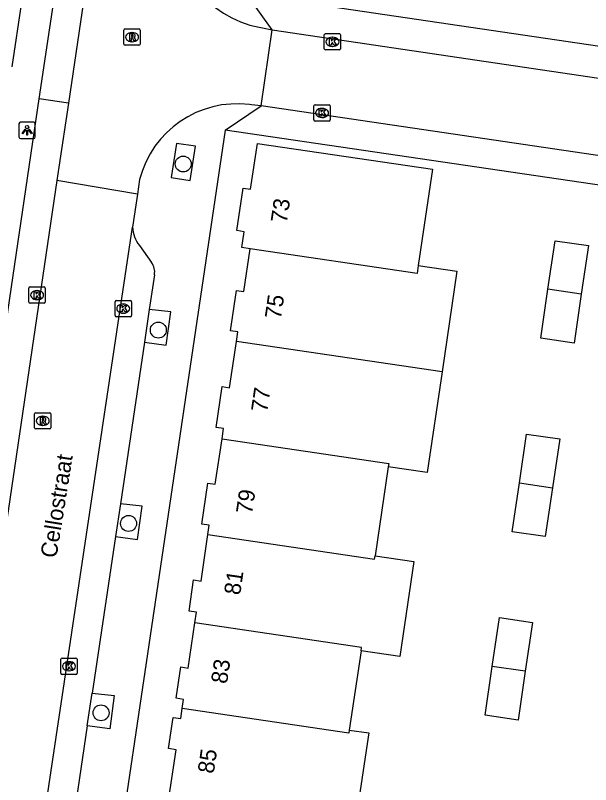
# Model space of a CAD drawing. Extents: x 164150 to 165261, y 382513 to 383432.
# Drawn here: x 164393.69 to 164428.99, y 382925.13 to 382972.36 of the extents above; entities that cross this region are included whole.
import ezdxf

# ---------------------------------------------------------------- set-up
doc = ezdxf.new("R2010")
doc.units = 0
for name, color, linetype in [('IMGEO_Boom', 7, 'Continuous'), ('IMGEO_Kolk', 7, 'Continuous'), ('IMGEO_Lichtpunt', 7, 'Continuous'), ('IMGEO_Openbare_ruimte_label', 7, 'Continuous'), ('IMGEO_Pand', 7, 'Continuous'), ('IMGEO_Pand_nummerreeks', 7, 'Continuous'), ('IMGEO_Parkeervlak_open', 7, 'Continuous'), ('IMGEO_Rijbaan_lokaal_open', 7, 'Continuous'), ('IMGEO_Rioolput', 7, 'Continuous'), ('IMGEO_Voetpad_open', 7, 'Continuous')]:
    doc.layers.add(name, color=color, linetype=linetype)

msp = doc.modelspace()

# ---------------------------------------------------------------- linework, layer by layer
at = {"layer": 'IMGEO_Boom'}
for centre in [(164403.987, 382963.232), (164402.46, 382953.036), (164400.635, 382941.165), (164398.944, 382929.538)]:
    msp.add_circle(centre, 0.489, dxfattribs=at)
at = {"layer": 'IMGEO_Kolk'}
for p, q in [((164412.645, 382970.309), (164412.645, 382971.161)), ((164412.72, 382971.235), (164413.572, 382971.235)), ((164413.646, 382971.161), (164413.646, 382970.309)), ((164413.133, 382971.015), (164413.158, 382971.015)), ((164413.572, 382970.235), (164412.72, 382970.235)), ((164413.156, 382970.455), (164413.131, 382970.455)), ((164412.009, 382965.942), (164412.009, 382966.794)), ((164412.084, 382966.868), (164412.936, 382966.868)), ((164412.497, 382966.648), (164412.522, 382966.648)), ((164413.01, 382966.794), (164413.01, 382965.942)), ((164412.52, 382966.088), (164412.495, 382966.088)), ((164412.936, 382965.868), (164412.084, 382965.868)), ((164394.519, 382954.76), (164394.519, 382955.612)), ((164394.594, 382955.686), (164395.446, 382955.686)), ((164395.52, 382955.612), (164395.52, 382954.76)), ((164395.007, 382955.466), (164395.032, 382955.466)), ((164395.446, 382954.686), (164394.594, 382954.686)), ((164395.03, 382954.906), (164395.005, 382954.906)), ((164399.805, 382953.928), (164399.805, 382954.78)), ((164399.88, 382954.854), (164400.732, 382954.854)), ((164400.293, 382954.634), (164400.318, 382954.634)), ((164400.806, 382954.78), (164400.806, 382953.928)), ((164400.732, 382953.854), (164399.88, 382953.854)), ((164400.316, 382954.074), (164400.291, 382954.074)), ((164396.477, 382931.973), (164396.477, 382932.825)), ((164396.552, 382932.899), (164397.404, 382932.899)), ((164396.965, 382932.679), (164396.99, 382932.679)), ((164397.478, 382932.825), (164397.478, 382931.973)), ((164396.988, 382932.119), (164396.963, 382932.119)), ((164397.404, 382931.899), (164396.552, 382931.899))]:
    msp.add_line(p, q, dxfattribs=at)
for points in [[(164412.645, 382970.309), (164412.645, 382971.161)], [(164412.72, 382971.235), (164413.572, 382971.235)], [(164413.646, 382971.161), (164413.646, 382970.309)], [(164412.966, 382970.935), (164413.089, 382970.935), (164413.089, 382970.784), (164413.219, 382970.935), (164413.383, 382970.935), (164413.237, 382970.784), (164413.39, 382970.535), (164413.238, 382970.535), (164413.153, 382970.699), (164413.089, 382970.632), (164413.089, 382970.535), (164412.966, 382970.535), (164412.966, 382970.935)], [(164413.572, 382970.235), (164412.72, 382970.235)], [(164412.009, 382965.942), (164412.009, 382966.794)], [(164412.084, 382966.868), (164412.936, 382966.868)], [(164412.33, 382966.568), (164412.453, 382966.568), (164412.453, 382966.417), (164412.583, 382966.568), (164412.747, 382966.568), (164412.601, 382966.417), (164412.754, 382966.168), (164412.602, 382966.168), (164412.517, 382966.332), (164412.453, 382966.265), (164412.453, 382966.168), (164412.33, 382966.168), (164412.33, 382966.568)], [(164413.01, 382966.794), (164413.01, 382965.942)], [(164412.936, 382965.868), (164412.084, 382965.868)], [(164394.519, 382954.76), (164394.519, 382955.612)], [(164394.594, 382955.686), (164395.446, 382955.686)], [(164395.52, 382955.612), (164395.52, 382954.76)], [(164394.84, 382955.386), (164394.963, 382955.386), (164394.963, 382955.235), (164395.093, 382955.386), (164395.257, 382955.386), (164395.111, 382955.235), (164395.264, 382954.986), (164395.112, 382954.986), (164395.027, 382955.15), (164394.963, 382955.083), (164394.963, 382954.986), (164394.84, 382954.986), (164394.84, 382955.386)], [(164395.446, 382954.686), (164394.594, 382954.686)], [(164399.805, 382953.928), (164399.805, 382954.78)], [(164399.88, 382954.854), (164400.732, 382954.854)], [(164400.806, 382954.78), (164400.806, 382953.928)], [(164400.126, 382954.554), (164400.249, 382954.554), (164400.249, 382954.403), (164400.379, 382954.554), (164400.543, 382954.554), (164400.397, 382954.403), (164400.55, 382954.154), (164400.398, 382954.154), (164400.313, 382954.318), (164400.249, 382954.251), (164400.249, 382954.154), (164400.126, 382954.154), (164400.126, 382954.554)], [(164400.732, 382953.854), (164399.88, 382953.854)], [(164396.477, 382931.973), (164396.477, 382932.825)], [(164396.552, 382932.899), (164397.404, 382932.899)], [(164396.798, 382932.599), (164396.921, 382932.599), (164396.921, 382932.448), (164397.051, 382932.599), (164397.215, 382932.599), (164397.069, 382932.448), (164397.222, 382932.199), (164397.07, 382932.199), (164396.985, 382932.363), (164396.921, 382932.296), (164396.921, 382932.199), (164396.798, 382932.199), (164396.798, 382932.599)], [(164397.478, 382932.825), (164397.478, 382931.973)], [(164397.404, 382931.899), (164396.552, 382931.899)]]:
    msp.add_lwpolyline(points, dxfattribs=at)
for centre, start, end in [((164412.722, 382971.159), 91.552, 178.448), ((164412.722, 382971.159), 91.552, 178.448), ((164413.57, 382971.159), 1.552, 88.448), ((164413.57, 382971.159), 1.552, 88.448), ((164412.722, 382970.311), 181.552, 268.448), ((164412.722, 382970.311), 181.552, 268.448), ((164413.57, 382970.311), 271.552, 358.448), ((164413.57, 382970.311), 271.552, 358.448), ((164412.086, 382966.792), 91.552, 178.448), ((164412.086, 382966.792), 91.552, 178.448), ((164412.934, 382966.792), 1.552, 88.448), ((164412.934, 382966.792), 1.552, 88.448), ((164412.086, 382965.944), 181.552, 268.448), ((164412.086, 382965.944), 181.552, 268.448), ((164412.934, 382965.944), 271.552, 358.448), ((164412.934, 382965.944), 271.552, 358.448), ((164394.596, 382955.61), 91.552, 178.448), ((164394.596, 382955.61), 91.552, 178.448), ((164395.444, 382955.61), 1.552, 88.448), ((164395.444, 382955.61), 1.552, 88.448), ((164394.596, 382954.762), 181.552, 268.448), ((164394.596, 382954.762), 181.552, 268.448), ((164395.444, 382954.762), 271.552, 358.448), ((164395.444, 382954.762), 271.552, 358.448), ((164399.882, 382954.778), 91.552, 178.448), ((164399.882, 382954.778), 91.552, 178.448), ((164400.73, 382954.778), 1.552, 88.448), ((164400.73, 382954.778), 1.552, 88.448), ((164399.882, 382953.93), 181.552, 268.448), ((164399.882, 382953.93), 181.552, 268.448), ((164400.73, 382953.93), 271.552, 358.448), ((164400.73, 382953.93), 271.552, 358.448), ((164396.554, 382932.823), 91.552, 178.448), ((164396.554, 382932.823), 91.552, 178.448), ((164397.402, 382932.823), 1.552, 88.448), ((164397.402, 382932.823), 1.552, 88.448), ((164396.554, 382931.975), 181.552, 268.448), ((164396.554, 382931.975), 181.552, 268.448), ((164397.402, 382931.975), 271.552, 358.448), ((164397.402, 382931.975), 271.552, 358.448)]:
    msp.add_arc(centre, 0.0765, start, end, dxfattribs=at)
for centre, major_axis, ratio, start_param, end_param in [((164413.132, 382970.735), (-0.387, 0.002), 0.722429, 4.712389, 7.853982), ((164413.157, 382970.735), (-0.39, 0.002), 0.717154, 1.570796, 4.712389), ((164412.496, 382966.368), (-0.387, 0.002), 0.722429, 4.712389, 7.853982), ((164412.521, 382966.368), (-0.39, 0.002), 0.717154, 1.570796, 4.712389), ((164395.006, 382955.186), (-0.387, 0.002), 0.722429, 4.712389, 7.853982), ((164395.031, 382955.186), (-0.39, 0.002), 0.717154, 1.570796, 4.712389), ((164400.292, 382954.354), (-0.387, 0.002), 0.722429, 4.712389, 7.853982), ((164400.317, 382954.354), (-0.39, 0.002), 0.717154, 1.570796, 4.712389), ((164396.964, 382932.399), (-0.387, 0.002), 0.722429, 4.712389, 7.853982), ((164396.989, 382932.399), (-0.39, 0.002), 0.717154, 1.570796, 4.712389)]:
    msp.add_ellipse(centre, major_axis=major_axis, ratio=ratio, start_param=start_param, end_param=end_param, dxfattribs=at)
at = {"layer": 'IMGEO_Lichtpunt'}
for p, q in [((164393.909, 382965.703), (164393.909, 382964.896)), ((164393.909, 382965.703), (164393.909, 382964.896)), ((164394.811, 382965.798), (164394.003, 382965.798)), ((164394.811, 382965.798), (164394.003, 382965.798)), ((164394.905, 382964.896), (164394.905, 382965.703)), ((164394.905, 382964.896), (164394.905, 382965.703)), ((164394.003, 382964.802), (164394.811, 382964.802)), ((164394.003, 382964.802), (164394.811, 382964.802))]:
    msp.add_line(p, q, dxfattribs=at)
for points in [[(164394.283, 382965.367), (164394.322, 382965.339), (164394.134, 382965.077), (164394.096, 382965.104), (164394.283, 382965.367)], [(164394.385, 382965.319), (164394.432, 382965.319), (164394.432, 382964.997), (164394.385, 382964.997), (164394.385, 382965.319)], [(164394.495, 382965.339), (164394.533, 382965.366), (164394.72, 382965.104), (164394.681, 382965.076), (164394.495, 382965.339)]]:
    msp.add_lwpolyline(points, dxfattribs=at)
msp.add_circle((164394.408, 382965.501), 0.0994, dxfattribs=at)
for centre, start, end in [((164394.003, 382965.703), 90, 180), ((164394.003, 382965.703), 90, 180), ((164394.811, 382965.703), 0, 90), ((164394.811, 382965.703), 0, 90), ((164394.003, 382964.896), 180, 270), ((164394.003, 382964.896), 180, 270), ((164394.811, 382964.896), 270, 0), ((164394.811, 382964.896), 270, 360)]:
    msp.add_arc(centre, 0.0946, start, end, dxfattribs=at)
at = {"layer": 'IMGEO_Pand'}
for points in [[(164408.091, 382958.021), (164407.589, 382958.097), (164407.736, 382959.075), (164407.281, 382959.143), (164407.67, 382961.751), (164408.125, 382961.681), (164408.545, 382964.496), (164419.288, 382962.906), (164418.415, 382957.004)], [(164426.369, 382955.541), (164426.808, 382958.517), (164428.857, 382958.234), (164428.412, 382955.238)], [(164407.253, 382952.345), (164407.338, 382952.921), (164406.884, 382952.988), (164407.25, 382955.475), (164407.705, 382955.408), (164408.091, 382958.021)], [(164418.415, 382957.004), (164418.341, 382956.503), (164408.091, 382958.021)], [(164418.415, 382957.004), (164420.787, 382956.653), (164419.872, 382950.476)], [(164428.412, 382955.238), (164427.968, 382952.241), (164425.925, 382952.531), (164426.369, 382955.541)], [(164428.412, 382955.238), (164426.369, 382955.541)], [(164406.37, 382946.365), (164406.462, 382946.988), (164406.006, 382947.057), (164406.38, 382949.567), (164406.833, 382949.501), (164407.253, 382952.345)], [(164419.872, 382950.476), (164407.253, 382952.345)], [(164419.872, 382950.476), (164418.957, 382944.298), (164416.574, 382944.65)], [(164424.616, 382943.662), (164425.058, 382946.655), (164427.096, 382946.358), (164426.651, 382943.361)], [(164405.503, 382940.497), (164405.587, 382941.066), (164405.132, 382941.132), (164405.507, 382943.641), (164405.957, 382943.574), (164406.37, 382946.365)], [(164406.37, 382946.365), (164416.603, 382944.848), (164416.574, 382944.65)], [(164416.574, 382944.65), (164415.764, 382939.179)], [(164426.651, 382943.361), (164426.207, 382940.363), (164424.173, 382940.661), (164424.616, 382943.662)], [(164424.616, 382943.662), (164426.651, 382943.361)], [(164404.7, 382935.064), (164404.796, 382935.716), (164404.343, 382935.784), (164404.628, 382937.7), (164405.079, 382937.631), (164405.503, 382940.497)], [(164405.503, 382940.497), (164415.735, 382938.981), (164415.764, 382939.179)], [(164415.764, 382939.179), (164418.147, 382938.826), (164417.284, 382932.998), (164414.9, 382933.351)], [(164422.953, 382932.391), (164423.394, 382935.382), (164425.424, 382935.085), (164424.98, 382932.091)], [(164403.923, 382929.8), (164404.006, 382930.366), (164403.553, 382930.447), (164403.838, 382932.357), (164404.291, 382932.291), (164404.7, 382935.064)], [(164414.9, 382933.351), (164414.929, 382933.549), (164404.7, 382935.064)], [(164414.9, 382933.351), (164414.179, 382928.484)], [(164424.98, 382932.091), (164424.535, 382929.096), (164422.511, 382929.391), (164422.953, 382932.391)], [(164424.98, 382932.091), (164422.953, 382932.391)], [(164403.128, 382924.422), (164403.549, 382927.272), (164403.093, 382927.341), (164403.379, 382929.257), (164403.833, 382929.19), (164403.923, 382929.8)], [(164414.179, 382928.484), (164414.15, 382928.286), (164403.923, 382929.8)], [(164414.179, 382928.484), (164415.369, 382928.308), (164414.544, 382922.733)]]:
    msp.add_lwpolyline(points, dxfattribs=at)
at = {"layer": 'IMGEO_Parkeervlak_open'}
for points in [[(164396.938, 382966.961), (164395.156, 382967.237)], [(164401.902, 382954.305), (164401.602, 382952.29)], [(164400.128, 382942.373), (164399.829, 382940.36)], [(164398.1, 382928.736), (164398.4, 382930.752)]]:
    msp.add_lwpolyline(points, dxfattribs=at)
at = {"layer": 'IMGEO_Rijbaan_lokaal_open'}
for points in [[(164398.238, 382975.73), (164396.938, 382966.961)], [(164394.057, 382973.175), (164393.467, 382969.194)], [(164408.655, 382971.626), (164408.848, 382971.589), (164409.455, 382971.474)], [(164408.777, 382966.8), (164409.455, 382971.474)], [(164409.455, 382971.474), (164452.852, 382965.04), (164453.027, 382965.023)], [(164396.938, 382966.961), (164396.356, 382963.04), (164396.236, 382962.229)], [(164408.777, 382966.8), (164408.17, 382966.868), (164408.046, 382966.882)], [(164452.341, 382960.375), (164452.149, 382960.409), (164408.777, 382966.8)], [(164396.236, 382962.229), (164391.231, 382928.476)], [(164401.178, 382961.379), (164396.236, 382962.229)], [(164401.312, 382962.274), (164401.178, 382961.379)], [(164401.178, 382961.379), (164400.876, 382959.355)], [(164390.296, 382888.433), (164395.748, 382925.028), (164400.876, 382959.355)]]:
    msp.add_lwpolyline(points, dxfattribs=at)
for centre, radius, start, end in [((164409.756, 382977.634), 6.108, 172.3026, 259.6163), ((164407.293, 382960.758), 6.17, 82.9906, 165.7762)]:
    msp.add_arc(centre, radius, start, end, dxfattribs=at)
at = {"layer": 'IMGEO_Rioolput'}
for p, q in [((164400.346, 382970.596), (164400.346, 382971.448)), ((164400.421, 382971.522), (164401.273, 382971.522)), ((164400.834, 382971.302), (164400.859, 382971.302)), ((164401.347, 382971.448), (164401.347, 382970.596)), ((164400.857, 382970.742), (164400.832, 382970.742)), ((164401.273, 382970.522), (164400.421, 382970.522)), ((164394.866, 382947.039), (164394.866, 382947.891)), ((164394.941, 382947.965), (164395.793, 382947.965)), ((164395.354, 382947.745), (164395.379, 382947.745)), ((164395.867, 382947.891), (164395.867, 382947.039)), ((164395.377, 382947.185), (164395.352, 382947.185)), ((164395.793, 382946.965), (164394.941, 382946.965))]:
    msp.add_line(p, q, dxfattribs=at)
for points in [[(164400.346, 382970.596), (164400.346, 382971.448)], [(164400.421, 382971.522), (164401.273, 382971.522)], [(164400.935, 382971.22), (164400.683, 382971.222), (164400.683, 382970.822)], [(164401.347, 382971.448), (164401.347, 382970.596)], [(164400.683, 382970.822), (164400.807, 382970.822), (164400.807, 382970.984), (164400.818, 382970.984)], [(164400.861, 382971.141), (164400.807, 382971.141), (164400.807, 382971.06)], [(164400.807, 382971.06), (164400.859, 382971.06)], [(164400.865, 382970.955), (164400.936, 382970.822), (164401.076, 382970.822), (164401.011, 382970.948)], [(164401.273, 382970.522), (164400.421, 382970.522)], [(164394.866, 382947.039), (164394.866, 382947.891)], [(164394.941, 382947.965), (164395.793, 382947.965)], [(164395.455, 382947.663), (164395.203, 382947.665), (164395.203, 382947.265)], [(164395.381, 382947.584), (164395.327, 382947.584), (164395.327, 382947.503)], [(164395.867, 382947.891), (164395.867, 382947.039)], [(164395.203, 382947.265), (164395.327, 382947.265), (164395.327, 382947.427), (164395.338, 382947.427)], [(164395.327, 382947.503), (164395.379, 382947.503)], [(164395.385, 382947.398), (164395.456, 382947.265), (164395.596, 382947.265), (164395.531, 382947.391)], [(164395.793, 382946.965), (164394.941, 382946.965)]]:
    msp.add_lwpolyline(points, dxfattribs=at)
for centre, radius, start, end in [((164400.423, 382971.446), 0.0765, 91.552, 178.448), ((164400.423, 382971.446), 0.0765, 91.552, 178.448), ((164400.934, 382971.11), 0.109, 350.3612, 89.416), ((164401.271, 382971.446), 0.0765, 1.552, 88.448), ((164401.271, 382971.446), 0.0765, 1.552, 88.448), ((164400.817, 382970.931), 0.0533, 26.0293, 88.6989), ((164400.843, 382971.249), 0.19, 274.7715, 282.9687), ((164400.867, 382971.045), 0.0964, 77.0061, 93.1865), ((164400.881, 382971.102), 0.0378, 276.6634, 79.6772), ((164400.932, 382971.11), 0.112, 277.5842, 350.9817), ((164400.916, 382970.895), 0.108, 29.5134, 73.7905), ((164400.423, 382970.598), 0.0765, 181.552, 268.448), ((164400.423, 382970.598), 0.0765, 181.552, 268.448), ((164401.271, 382970.598), 0.0765, 271.552, 358.448), ((164401.271, 382970.598), 0.0765, 271.552, 358.448), ((164394.943, 382947.889), 0.0765, 91.552, 178.448), ((164394.943, 382947.889), 0.0765, 91.552, 178.448), ((164395.387, 382947.488), 0.0964, 77.0061, 93.1865), ((164395.401, 382947.545), 0.0378, 276.6634, 79.6772), ((164395.454, 382947.553), 0.109, 350.3612, 89.416), ((164395.791, 382947.889), 0.0765, 1.552, 88.448), ((164395.791, 382947.889), 0.0765, 1.552, 88.448), ((164395.337, 382947.374), 0.0533, 26.0293, 88.6989), ((164395.363, 382947.692), 0.19, 274.7715, 282.9687), ((164395.452, 382947.553), 0.112, 277.5842, 350.9817), ((164395.436, 382947.338), 0.108, 29.5134, 73.7905), ((164394.943, 382947.041), 0.0765, 181.552, 268.448), ((164394.943, 382947.041), 0.0765, 181.552, 268.448), ((164395.791, 382947.041), 0.0765, 271.552, 358.448), ((164395.791, 382947.041), 0.0765, 271.552, 358.448)]:
    msp.add_arc(centre, radius, start, end, dxfattribs=at)
for centre, major_axis, ratio, start_param, end_param in [((164400.833, 382971.022), (-0.387, 0.002), 0.722429, 4.712389, 7.853982), ((164400.858, 382971.022), (-0.39, 0.002), 0.717154, 1.570796, 4.712389), ((164395.353, 382947.465), (-0.387, 0.002), 0.722429, 4.712389, 7.853982), ((164395.378, 382947.465), (-0.39, 0.002), 0.717154, 1.570796, 4.712389)]:
    msp.add_ellipse(centre, major_axis=major_axis, ratio=ratio, start_param=start_param, end_param=end_param, dxfattribs=at)
at = {"layer": 'IMGEO_Voetpad_open'}
for points in [[(164464.884, 383024.193), (164464.77, 383023.421), (164456.354, 382966.497), (164407.897, 382973.658)], [(164395.156, 382967.237), (164396.45, 382975.965)], [(164409.455, 382971.474), (164407.897, 382973.658)], [(164389.851, 382931.455), (164390.146, 382933.429), (164390.293, 382934.417), (164395.156, 382967.237)], [(164406.562, 382965.305), (164408.777, 382966.8)], [(164406.562, 382965.305), (164395.217, 382888.733)], [(164444.484, 382885.938), (164455.128, 382958.161), (164406.562, 382965.305)], [(164404.732, 382964.323), (164403.571, 382964.484), (164403.248, 382962.412), (164404.417, 382962.229), (164404.732, 382964.323)], [(164401.299, 382958.237), (164402.044, 382957.182)], [(164402.218, 382956.43), (164401.902, 382954.305)], [(164401.602, 382952.29), (164402.936, 382952.107), (164403.221, 382954.164), (164401.902, 382954.305)], [(164401.602, 382952.29), (164400.128, 382942.373)], [(164399.829, 382940.36), (164401.173, 382940.175), (164401.458, 382942.232), (164400.128, 382942.373)], [(164399.829, 382940.36), (164398.4, 382930.752)], [(164398.4, 382930.752), (164399.759, 382930.606), (164399.474, 382928.549), (164398.1, 382928.736)], [(164398.1, 382928.736), (164397.524, 382924.861), (164396.585, 382918.54)]]:
    msp.add_lwpolyline(points, dxfattribs=at)
for centre, radius, start, end in [((164402.882, 382959.475), 2.01, 183.4218, 218.0268), ((164401.287, 382956.611), 0.948, 349.0035, 37.0525)]:
    msp.add_arc(centre, radius, start, end, dxfattribs=at)

# ---------------------------------------------------------------- texts
at = {"layer": 'IMGEO_Openbare_ruimte_label'}
msp.add_text('Cellostraat', height=1, rotation=80.9142, dxfattribs=at).set_placement((164396.203, 382939.002))
at = {"layer": 'IMGEO_Pand_nummerreeks'}
for s, rotation, p in [('73', 81.5147, (164410.338, 382959.568)), ('75', 81.5949, (164409.975, 382953.668)), ('77', 81.6006, (164409.132, 382947.959)), ('79', 81.5835, (164408.208, 382941.703)), ('81', 81.5892, (164407.473, 382936.731)), ('83', 81.6121, (164406.67, 382931.285)), ('85', 81.6006, (164405.855, 382925.772))]:
    msp.add_text(s, height=1, rotation=rotation, dxfattribs=at).set_placement(p)

doc.saveas('drawing.dxf')
